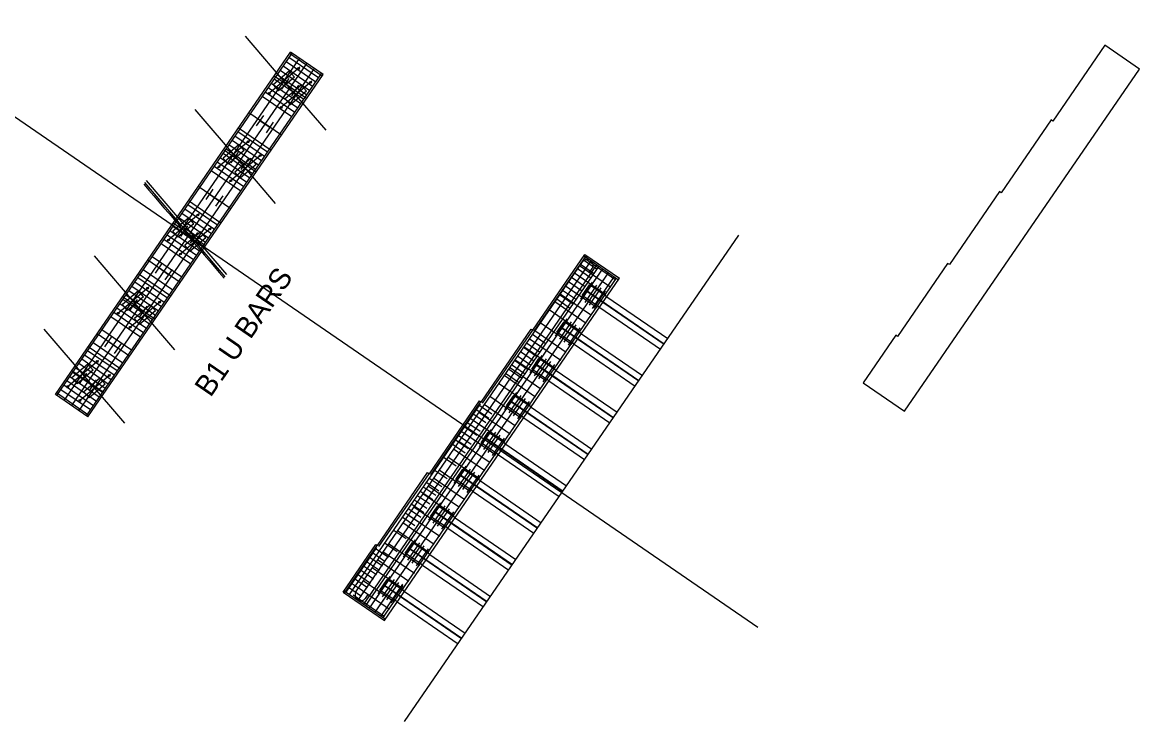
# Model space of a CAD drawing. Extents: x 2378999 to 2381348, y 331302 to 333122.
# Drawn here: x 2379615.5 to 2379721.8, y 332001.2 to 332067.7 of the extents above; entities that cross this region are included whole.
import ezdxf

# ---------------------------------------------------------------- set-up
doc = ezdxf.new("R2010")
doc.units = 0
for name, color, linetype in [('Arrowhead Terminators', 7, 'Continuous'), ('Dimension Lines', 7, 'Continuous'), ('Dimension Lines CELL', 7, 'Continuous'), ('Mis Work Point CELL', 7, 'Continuous'), ('P_SMU_Bent_Cap', 7, 'Continuous'), ('P_SMU_D_Deck_Outline', 7, 'Continuous'), ('P_SMU_Girder_Concrete', 7, 'Continuous'), ('P_SMU_Mis_L_Lines', 7, 'Continuous'), ('P_SMU_Mis_Long_Chord', 7, 'Continuous'), ('P_SMU_Rebar_U_Bar', 7, 'Continuous'), ('Plan Sheet CELL', 7, 'Continuous'), ('Rebar Lines', 7, 'Continuous'), ('Scratch_Level_0', 7, 'Continuous'), ('Sup Concrete Slab Lines', 7, 'Continuous'), ('Text', 7, 'Continuous')]:
    doc.layers.add(name, color=color, linetype=linetype)

msp = doc.modelspace()

# ---------------------------------------------------------------- linework, layer by layer
at = {"layer": 'Arrowhead Terminators'}
for p, q in [((2379647.28, 332013.54), (2379668.84, 332044.91)), ((2379647.48, 332012.73), (2379669.65, 332045.02)), ((2379648.03, 332012.36), (2379670.2, 332044.64)), ((2379648.23, 332012.22), (2379670.41, 332044.5)), ((2379648.57, 332011.98), (2379670.75, 332044.26)), ((2379669.5, 332043.92), (2379669.75, 332044.28)), ((2379649.12, 332011.6), (2379671.3, 332043.88)), ((2379649.88, 332011.08), (2379672.06, 332043.36)), ((2379646.68, 332013.28), (2379659.13, 332031.42)), ((2379646.36, 332013.5), (2379649.28, 332017.76)), ((2379648.19, 332012.91), (2379648.44, 332013.27))]:
    msp.add_line(p, q, dxfattribs=at)
for centre, start, end in [((2379669.29, 332044.6), 325.5093, 145.5093), ((2379647.74, 332013.23), 145.5093, 325.5093)]:
    msp.add_arc(centre, 0.552, start, end, dxfattribs=at)
at = {"layer": 'Dimension Lines'}
for p, q in [((2379669.01, 332045.26), (2379672, 332043.2)), ((2379668.54, 332044.57), (2379671.53, 332042.52)), ((2379668.07, 332043.88), (2379671.05, 332041.83)), ((2379667.22, 332042.65), (2379670.21, 332040.59)), ((2379668.66, 332041.36), (2379669.79, 332043)), ((2379669.07, 332041.07), (2379670.2, 332042.72)), ((2379669.48, 332040.79), (2379670.61, 332042.44)), ((2379669.89, 332040.51), (2379671.02, 332042.15)), ((2379666.18, 332041.14), (2379669.17, 332039.08)), ((2379666.7, 332041.89), (2379669.69, 332039.84)), ((2379665.66, 332040.38), (2379668.65, 332038.33)), ((2379664.81, 332039.14), (2379667.8, 332037.09)), ((2379666.25, 332037.85), (2379667.38, 332039.5)), ((2379666.66, 332037.57), (2379667.79, 332039.22)), ((2379667.07, 332037.29), (2379668.21, 332038.93)), ((2379664.29, 332038.39), (2379667.28, 332036.34)), ((2379667.49, 332037), (2379668.62, 332038.65)), ((2379663.25, 332036.88), (2379666.24, 332034.82)), ((2379663.77, 332037.63), (2379666.76, 332035.58)), ((2379662.4, 332035.64), (2379665.39, 332033.59)), ((2379663.84, 332034.35), (2379664.98, 332036)), ((2379664.25, 332034.07), (2379665.39, 332035.71)), ((2379661.89, 332034.89), (2379664.87, 332032.83)), ((2379664.67, 332033.78), (2379665.8, 332035.43)), ((2379665.08, 332033.5), (2379666.21, 332035.15)), ((2379661.37, 332034.13), (2379664.35, 332032.08)), ((2379660.85, 332033.37), (2379663.84, 332031.32)), ((2379661.44, 332030.85), (2379662.57, 332032.49)), ((2379659.48, 332031.38), (2379662.47, 332029.33)), ((2379660, 332032.14), (2379662.99, 332030.09)), ((2379661.85, 332030.56), (2379662.98, 332032.21)), ((2379662.26, 332030.28), (2379663.39, 332031.93)), ((2379662.67, 332030), (2379663.8, 332031.65)), ((2379658.96, 332030.63), (2379661.95, 332028.57)), ((2379658.44, 332029.87), (2379661.43, 332027.82)), ((2379657.59, 332028.63), (2379660.58, 332026.58)), ((2379659.03, 332027.34), (2379660.16, 332028.99)), ((2379659.44, 332027.06), (2379660.57, 332028.71)), ((2379659.85, 332026.78), (2379660.99, 332028.43)), ((2379657.07, 332027.88), (2379660.06, 332025.83)), ((2379660.27, 332026.49), (2379661.4, 332028.14)), ((2379656.03, 332026.37), (2379659.02, 332024.32)), ((2379656.55, 332027.12), (2379659.54, 332025.07)), ((2379655.18, 332025.13), (2379658.17, 332023.08)), ((2379656.62, 332023.84), (2379657.76, 332025.49)), ((2379657.03, 332023.56), (2379658.17, 332025.21)), ((2379654.67, 332024.38), (2379657.65, 332022.32)), ((2379657.45, 332023.27), (2379658.58, 332024.92)), ((2379657.86, 332022.99), (2379658.99, 332024.64)), ((2379654.15, 332023.62), (2379657.13, 332021.57)), ((2379653.63, 332022.87), (2379656.62, 332020.81)), ((2379654.22, 332020.34), (2379655.35, 332021.99)), ((2379652.26, 332020.87), (2379655.25, 332018.82)), ((2379652.78, 332021.63), (2379655.77, 332019.58)), ((2379654.63, 332020.05), (2379655.76, 332021.7)), ((2379655.04, 332019.77), (2379656.17, 332021.42)), ((2379655.45, 332019.49), (2379656.58, 332021.14)), ((2379651.74, 332020.12), (2379654.73, 332018.07)), ((2379651.22, 332019.36), (2379654.21, 332017.31)), ((2379650.37, 332018.13), (2379653.36, 332016.07)), ((2379651.81, 332016.83), (2379652.94, 332018.48)), ((2379652.22, 332016.55), (2379653.35, 332018.2)), ((2379652.63, 332016.27), (2379653.77, 332017.92)), ((2379653.05, 332015.99), (2379654.18, 332017.63)), ((2379649.33, 332016.62), (2379652.32, 332014.56)), ((2379649.85, 332017.37), (2379652.84, 332015.32)), ((2379648.81, 332015.86), (2379651.8, 332013.81)), ((2379647.96, 332014.62), (2379650.95, 332012.57)), ((2379649.4, 332013.33), (2379650.54, 332014.98)), ((2379649.81, 332013.05), (2379650.95, 332014.7)), ((2379650.23, 332012.77), (2379651.36, 332014.41)), ((2379647.49, 332013.94), (2379650.48, 332011.88)), ((2379650.64, 332012.48), (2379651.77, 332014.13)), ((2379647.02, 332013.25), (2379650.01, 332011.2))]:
    msp.add_line(p, q, dxfattribs=at)
at = {"layer": 'Dimension Lines CELL'}
msp.add_line((2379507.79, 332132.25), (2379685.49, 332010.16), dxfattribs=at)
at = {"layer": 'Mis Work Point CELL'}
for p, q in [((2379619.54, 332031.73), (2379641.91, 332064.28)), ((2379620.24, 332031.25), (2379642.6, 332063.8)), ((2379643.3, 332063.32), (2379620.93, 332030.77)), ((2379651.9, 332001.18), (2379683.69, 332047.45))]:
    msp.add_line(p, q, dxfattribs=at)
at = {"layer": 'P_SMU_Bent_Cap'}
for p, q in [((2379641.95, 332063.43), (2379638.91, 332060.83)), ((2379643.09, 332062.1), (2379640.04, 332059.5)), ((2379637.16, 332056.46), (2379634.12, 332053.86)), ((2379638.3, 332055.13), (2379635.26, 332052.53)), ((2379632.37, 332049.49), (2379629.33, 332046.89)), ((2379633.51, 332048.16), (2379630.47, 332045.56)), ((2379627.59, 332042.52), (2379624.54, 332039.92)), ((2379628.72, 332041.19), (2379625.68, 332038.59)), ((2379622.8, 332035.55), (2379619.76, 332032.95)), ((2379623.93, 332034.22), (2379620.89, 332031.62))]:
    msp.add_line(p, q, dxfattribs=at)
at = {"layer": 'P_SMU_D_Deck_Outline'}
for p, q in [((2379640.94, 332063.06), (2379639.42, 332061.76)), ((2379641.43, 332062.49), (2379639.91, 332061.19)), ((2379641.43, 332062.49), (2379640.94, 332063.06)), ((2379639.91, 332061.19), (2379639.42, 332061.76)), ((2379642.08, 332061.73), (2379640.56, 332060.43)), ((2379642.57, 332061.16), (2379641.05, 332059.86)), ((2379642.57, 332061.16), (2379642.08, 332061.73)), ((2379641.05, 332059.86), (2379640.56, 332060.43)), ((2379636.16, 332056.09), (2379634.64, 332054.79)), ((2379636.64, 332055.52), (2379636.16, 332056.09)), ((2379635.12, 332054.22), (2379634.64, 332054.79)), ((2379636.64, 332055.52), (2379635.12, 332054.22)), ((2379637.29, 332054.76), (2379635.77, 332053.46)), ((2379637.78, 332054.19), (2379637.29, 332054.76)), ((2379637.78, 332054.19), (2379636.26, 332052.89)), ((2379636.26, 332052.89), (2379635.77, 332053.46)), ((2379631.37, 332049.12), (2379629.85, 332047.83)), ((2379631.86, 332048.55), (2379630.34, 332047.26)), ((2379631.86, 332048.55), (2379631.37, 332049.12)), ((2379630.34, 332047.26), (2379629.85, 332047.83)), ((2379632.51, 332047.79), (2379630.99, 332046.5)), ((2379632.99, 332047.22), (2379632.51, 332047.79)), ((2379631.47, 332045.92), (2379630.99, 332046.5)), ((2379632.99, 332047.22), (2379631.47, 332045.92)), ((2379626.58, 332042.16), (2379625.06, 332040.86)), ((2379627.07, 332041.59), (2379626.58, 332042.16)), ((2379627.07, 332041.59), (2379625.55, 332040.29)), ((2379625.55, 332040.29), (2379625.06, 332040.86)), ((2379627.72, 332040.83), (2379626.2, 332039.53)), ((2379628.21, 332040.26), (2379626.69, 332038.96)), ((2379628.21, 332040.26), (2379627.72, 332040.83)), ((2379626.69, 332038.96), (2379626.2, 332039.53)), ((2379621.79, 332035.19), (2379620.27, 332033.89)), ((2379622.28, 332034.62), (2379620.76, 332033.32)), ((2379622.28, 332034.62), (2379621.79, 332035.19)), ((2379620.76, 332033.32), (2379620.27, 332033.89)), ((2379622.93, 332033.86), (2379621.41, 332032.56)), ((2379623.42, 332033.29), (2379622.93, 332033.86)), ((2379621.9, 332031.99), (2379621.41, 332032.56)), ((2379623.42, 332033.29), (2379621.9, 332031.99))]:
    msp.add_line(p, q, dxfattribs=at)
for centre in [(2379641.82, 332063.32), (2379642.96, 332061.99), (2379639.03, 332060.94), (2379640.17, 332059.61), (2379637.03, 332056.35), (2379638.17, 332055.02), (2379634.25, 332053.97), (2379635.38, 332052.64), (2379632.25, 332049.38), (2379633.38, 332048.05), (2379629.46, 332047), (2379630.6, 332045.67), (2379627.46, 332042.41), (2379628.6, 332041.08), (2379624.67, 332040.03), (2379625.81, 332038.7), (2379622.67, 332035.44), (2379623.81, 332034.11), (2379619.88, 332033.06), (2379621.02, 332031.73)]:
    msp.add_circle(centre, 0.0833, dxfattribs=at)
at = {"layer": 'P_SMU_Girder_Concrete'}
for p, q in [((2379640.24, 332061.36), (2379640.93, 332062.36)), ((2379640.58, 332061.86), (2379641.51, 332061.22)), ((2379641.17, 332060.71), (2379641.86, 332061.72)), ((2379637.83, 332057.85), (2379638.52, 332058.86)), ((2379638.17, 332058.35), (2379639.11, 332057.71)), ((2379638.76, 332057.21), (2379639.45, 332058.21)), ((2379635.42, 332054.35), (2379636.11, 332055.35)), ((2379635.77, 332054.85), (2379636.7, 332054.21)), ((2379636.36, 332053.71), (2379637.05, 332054.71)), ((2379633.02, 332050.85), (2379633.71, 332051.85)), ((2379633.36, 332051.35), (2379634.29, 332050.71)), ((2379633.95, 332050.21), (2379634.64, 332051.21)), ((2379630.61, 332047.34), (2379631.3, 332048.35)), ((2379630.95, 332047.85), (2379631.89, 332047.2)), ((2379631.54, 332046.7), (2379632.23, 332047.71)), ((2379628.2, 332043.84), (2379628.89, 332044.84)), ((2379628.55, 332044.34), (2379629.48, 332043.7)), ((2379629.14, 332043.2), (2379629.83, 332044.2)), ((2379668.81, 332041.73), (2379669.5, 332042.73)), ((2379669.14, 332042.21), (2379676.58, 332037.1)), ((2379669.17, 332042.24), (2379676.6, 332037.13)), ((2379671.15, 332041.6), (2379669.5, 332042.73)), ((2379625.8, 332040.34), (2379626.49, 332041.34)), ((2379670.46, 332040.59), (2379668.81, 332041.73)), ((2379671.15, 332041.6), (2379676.93, 332037.62)), ((2379626.14, 332040.84), (2379627.07, 332040.2)), ((2379626.73, 332039.7), (2379627.42, 332040.7)), ((2379670.46, 332040.59), (2379676.25, 332036.62)), ((2379666.4, 332038.22), (2379667.09, 332039.23)), ((2379668.74, 332038.09), (2379667.09, 332039.23)), ((2379623.39, 332036.84), (2379624.08, 332037.84)), ((2379668.05, 332037.09), (2379666.4, 332038.22)), ((2379666.73, 332038.71), (2379674.17, 332033.6)), ((2379666.76, 332038.74), (2379674.2, 332033.63)), ((2379668.74, 332038.09), (2379674.53, 332034.12)), ((2379623.73, 332037.34), (2379624.67, 332036.7)), ((2379624.32, 332036.19), (2379625.01, 332037.2)), ((2379668.05, 332037.09), (2379673.84, 332033.11)), ((2379664, 332034.72), (2379664.68, 332035.72)), ((2379666.33, 332034.59), (2379664.68, 332035.72)), ((2379665.64, 332033.59), (2379664, 332034.72)), ((2379664.33, 332035.2), (2379671.77, 332030.09)), ((2379664.35, 332035.24), (2379671.79, 332030.13)), ((2379666.33, 332034.59), (2379672.12, 332030.61)), ((2379620.98, 332033.33), (2379621.67, 332034.34)), ((2379621.33, 332033.83), (2379622.26, 332033.19)), ((2379621.92, 332032.69), (2379622.61, 332033.69)), ((2379665.64, 332033.59), (2379671.43, 332029.61)), ((2379661.59, 332031.22), (2379662.28, 332032.22)), ((2379661.92, 332031.7), (2379669.36, 332026.59)), ((2379661.95, 332031.74), (2379669.38, 332026.63)), ((2379663.93, 332031.09), (2379662.28, 332032.22)), ((2379663.24, 332030.08), (2379661.59, 332031.22)), ((2379663.93, 332031.09), (2379669.71, 332027.11)), ((2379663.24, 332030.08), (2379669.03, 332026.11)), ((2379659.18, 332027.71), (2379659.87, 332028.72)), ((2379659.52, 332028.2), (2379666.95, 332023.09)), ((2379659.54, 332028.23), (2379666.98, 332023.12)), ((2379661.52, 332027.58), (2379659.87, 332028.72)), ((2379660.83, 332026.58), (2379659.18, 332027.71)), ((2379661.52, 332027.58), (2379667.31, 332023.61)), ((2379660.83, 332026.58), (2379666.62, 332022.6)), ((2379656.78, 332024.21), (2379657.46, 332025.21)), ((2379659.11, 332024.08), (2379657.46, 332025.21)), ((2379658.42, 332023.08), (2379656.78, 332024.21)), ((2379657.11, 332024.69), (2379664.55, 332019.59)), ((2379657.13, 332024.73), (2379664.57, 332019.62)), ((2379659.11, 332024.08), (2379664.9, 332020.1)), ((2379658.42, 332023.08), (2379664.21, 332019.1)), ((2379654.37, 332020.71), (2379655.06, 332021.71)), ((2379654.7, 332021.19), (2379662.14, 332016.08)), ((2379654.73, 332021.23), (2379662.16, 332016.12)), ((2379656.71, 332020.58), (2379655.06, 332021.71)), ((2379656.02, 332019.58), (2379654.37, 332020.71)), ((2379656.71, 332020.58), (2379662.5, 332016.6)), ((2379656.02, 332019.58), (2379661.81, 332015.6)), ((2379651.96, 332017.2), (2379652.65, 332018.21)), ((2379652.3, 332017.69), (2379659.73, 332012.58)), ((2379652.32, 332017.72), (2379659.76, 332012.61)), ((2379654.3, 332017.07), (2379652.65, 332018.21)), ((2379653.61, 332016.07), (2379651.96, 332017.2)), ((2379654.3, 332017.07), (2379660.09, 332013.1)), ((2379653.61, 332016.07), (2379659.4, 332012.1)), ((2379649.56, 332013.7), (2379650.24, 332014.7)), ((2379651.89, 332013.57), (2379650.24, 332014.7)), ((2379651.2, 332012.57), (2379649.56, 332013.7)), ((2379649.89, 332014.19), (2379657.33, 332009.08)), ((2379649.91, 332014.22), (2379657.35, 332009.11)), ((2379651.89, 332013.57), (2379657.68, 332009.6)), ((2379651.2, 332012.57), (2379656.99, 332008.59))]:
    msp.add_line(p, q, dxfattribs=at)
at = {"layer": 'P_SMU_Mis_L_Lines'}
for p, q in [((2379641, 332061.46), (2379636.78, 332066.4)), ((2379644.43, 332057.45), (2379641, 332061.46)), ((2379636.21, 332054.49), (2379631.99, 332059.43)), ((2379639.64, 332050.48), (2379636.21, 332054.49)), ((2379631.42, 332047.52), (2379627.2, 332052.46)), ((2379634.85, 332043.51), (2379631.42, 332047.52)), ((2379626.63, 332040.56), (2379622.42, 332045.49)), ((2379630.06, 332036.54), (2379626.63, 332040.56)), ((2379621.85, 332033.59), (2379617.63, 332038.52)), ((2379625.28, 332029.57), (2379621.85, 332033.59))]:
    msp.add_line(p, q, dxfattribs=at)
at = {"layer": 'P_SMU_Mis_Long_Chord'}
msp.add_arc((2385014.25, 336646.34), 7080, 220.456783, 220.552053, dxfattribs=at)
at = {"layer": 'P_SMU_Rebar_U_Bar'}
for p, q in [((2379643.73, 332062.42), (2379640.91, 332064.36)), ((2379643.16, 332061.6), (2379640.35, 332063.53)), ((2379643.45, 332062.01), (2379640.63, 332063.95)), ((2379642.31, 332060.36), (2379639.5, 332062.3)), ((2379642.6, 332060.78), (2379639.78, 332062.71)), ((2379642.88, 332061.19), (2379640.06, 332063.12)), ((2379641.75, 332059.54), (2379638.93, 332061.47)), ((2379642.03, 332059.95), (2379639.21, 332061.89)), ((2379641.18, 332058.71), (2379638.37, 332060.65)), ((2379641.46, 332059.13), (2379638.65, 332061.06)), ((2379638.87, 332055.35), (2379636.05, 332057.28)), ((2379638.02, 332054.11), (2379635.2, 332056.05)), ((2379638.3, 332054.52), (2379635.49, 332056.46)), ((2379638.59, 332054.94), (2379635.77, 332056.87)), ((2379637.17, 332052.88), (2379634.35, 332054.81)), ((2379637.45, 332053.29), (2379634.64, 332055.22)), ((2379637.74, 332053.7), (2379634.92, 332055.64)), ((2379636.6, 332052.05), (2379633.79, 332053.99)), ((2379636.89, 332052.46), (2379634.07, 332054.4)), ((2379636.32, 332051.64), (2379633.51, 332053.57)), ((2379633.54, 332047.59), (2379630.72, 332049.52)), ((2379633.82, 332048), (2379631, 332049.93)), ((2379634.1, 332048.41), (2379631.29, 332050.35)), ((2379632.97, 332046.76), (2379630.15, 332048.7)), ((2379633.25, 332047.18), (2379630.44, 332049.11)), ((2379632.12, 332045.53), (2379629.31, 332047.46)), ((2379632.4, 332045.94), (2379629.59, 332047.87)), ((2379632.69, 332046.35), (2379629.87, 332048.29)), ((2379631.56, 332044.7), (2379628.74, 332046.64)), ((2379631.84, 332045.11), (2379629.02, 332047.05)), ((2379630.71, 332043.47), (2379627.89, 332045.4)), ((2379629.86, 332042.23), (2379627.04, 332044.16)), ((2379668.35, 332044.3), (2379669.59, 332043.45)), ((2379668.63, 332044.71), (2379669.87, 332043.86)), ((2379668.81, 332043.78), (2379669.65, 332045.02)), ((2379668.92, 332045.12), (2379670.15, 332044.27)), ((2379669.35, 332043.4), (2379670.2, 332044.64)), ((2379669.9, 332043.03), (2379670.75, 332044.26)), ((2379629.34, 332041.47), (2379626.52, 332043.41)), ((2379667.78, 332043.47), (2379669.02, 332042.62)), ((2379668.07, 332043.88), (2379669.3, 332043.03)), ((2379669.78, 332040.48), (2379671.85, 332043.51)), ((2379670.45, 332042.65), (2379671.3, 332043.88)), ((2379628.49, 332040.24), (2379625.67, 332042.17)), ((2379628.77, 332040.65), (2379625.95, 332042.59)), ((2379629.05, 332041.06), (2379626.24, 332043)), ((2379666.93, 332042.23), (2379668.17, 332041.39)), ((2379667.22, 332042.65), (2379668.45, 332041.8)), ((2379667.5, 332043.06), (2379668.74, 332042.21)), ((2379627.92, 332039.41), (2379625.11, 332041.35)), ((2379628.2, 332039.83), (2379625.39, 332041.76)), ((2379666.37, 332041.41), (2379667.6, 332040.56)), ((2379666.65, 332041.82), (2379667.89, 332040.97)), ((2379627.07, 332038.18), (2379624.26, 332040.11)), ((2379627.36, 332038.59), (2379624.54, 332040.52)), ((2379627.64, 332039), (2379624.82, 332040.94)), ((2379626.79, 332037.77), (2379623.97, 332039.7)), ((2379625.94, 332036.53), (2379623.12, 332038.46)), ((2379664.06, 332038.04), (2379665.29, 332037.2)), ((2379625.09, 332035.29), (2379622.27, 332037.23)), ((2379663.21, 332036.81), (2379664.44, 332035.96)), ((2379663.49, 332037.22), (2379664.73, 332036.37)), ((2379663.77, 332037.63), (2379665.01, 332036.78)), ((2379624, 332033.71), (2379621.19, 332035.65)), ((2379624.29, 332034.13), (2379621.47, 332036.06)), ((2379624.57, 332034.54), (2379621.75, 332036.47)), ((2379662.64, 332035.98), (2379663.88, 332035.13)), ((2379662.92, 332036.4), (2379664.16, 332035.55)), ((2379623.44, 332032.89), (2379620.62, 332034.82)), ((2379623.72, 332033.3), (2379620.91, 332035.24)), ((2379661.79, 332034.75), (2379663.03, 332033.9)), ((2379662.07, 332035.16), (2379663.31, 332034.31)), ((2379662.36, 332035.57), (2379663.59, 332034.72)), ((2379622.59, 332031.65), (2379619.77, 332033.59)), ((2379622.87, 332032.06), (2379620.06, 332034)), ((2379623.16, 332032.48), (2379620.34, 332034.41)), ((2379661.51, 332034.34), (2379662.74, 332033.49)), ((2379622.02, 332030.83), (2379619.21, 332032.76)), ((2379622.31, 332031.24), (2379619.49, 332033.18)), ((2379658.41, 332030.5), (2379659.64, 332029.65)), ((2379658.69, 332030.91), (2379659.93, 332030.06)), ((2379658.97, 332031.33), (2379660.21, 332030.48)), ((2379657.56, 332029.27), (2379658.79, 332028.42)), ((2379657.84, 332029.68), (2379659.08, 332028.83)), ((2379658.12, 332030.09), (2379659.36, 332029.24)), ((2379656.99, 332028.44), (2379658.23, 332027.59)), ((2379657.27, 332028.85), (2379658.51, 332028)), ((2379656.42, 332027.62), (2379657.66, 332026.77)), ((2379656.71, 332028.03), (2379657.94, 332027.18)), ((2379655.57, 332026.38), (2379656.81, 332025.53)), ((2379654.72, 332025.14), (2379655.96, 332024.3)), ((2379653.92, 332023.98), (2379655.16, 332023.13)), ((2379654.21, 332024.39), (2379655.44, 332023.54)), ((2379653.36, 332023.15), (2379654.59, 332022.3)), ((2379653.64, 332023.56), (2379654.88, 332022.72)), ((2379652.51, 332021.92), (2379653.74, 332021.07)), ((2379652.79, 332022.33), (2379654.03, 332021.48)), ((2379653.07, 332022.74), (2379654.31, 332021.89)), ((2379651.94, 332021.09), (2379653.18, 332020.24)), ((2379652.22, 332021.5), (2379653.46, 332020.65)), ((2379651.66, 332020.68), (2379652.89, 332019.83)), ((2379650.81, 332019.44), (2379652.04, 332018.59)), ((2379649.12, 332017.67), (2379650.36, 332016.82)), ((2379649.96, 332018.21), (2379651.19, 332017.36)), ((2379648.55, 332016.85), (2379649.79, 332016)), ((2379648.84, 332017.26), (2379650.07, 332016.41)), ((2379647.7, 332015.61), (2379648.94, 332014.76)), ((2379647.99, 332016.02), (2379649.22, 332015.17)), ((2379648.27, 332016.43), (2379649.51, 332015.59)), ((2379646.68, 332013.28), (2379647.53, 332014.52)), ((2379647.14, 332014.79), (2379648.37, 332013.94)), ((2379647.42, 332015.2), (2379648.66, 332014.35)), ((2379646.57, 332013.96), (2379647.81, 332013.11)), ((2379646.86, 332014.37), (2379648.09, 332013.52)), ((2379647.48, 332012.73), (2379648.33, 332013.97)), ((2379648.03, 332012.36), (2379648.87, 332013.59)), ((2379649.67, 332011.22), (2379651.75, 332014.25)), ((2379648.57, 332011.98), (2379649.42, 332013.22)), ((2379649.12, 332011.6), (2379649.97, 332012.84))]:
    msp.add_line(p, q, dxfattribs=at)
at = {"layer": 'Plan Sheet CELL'}
msp.add_line((2379635, 332043.72), (2379627.35, 332052.67), dxfattribs=at)
at = {"layer": 'Rebar Lines'}
for p, q in [((2379642.59, 332060.47), (2379639.5, 332062.6)), ((2379640.19, 332056.97), (2379637.1, 332059.1)), ((2379637.78, 332053.47), (2379634.69, 332055.59)), ((2379635.37, 332049.97), (2379632.28, 332052.09)), ((2379632.97, 332046.46), (2379629.88, 332048.59)), ((2379630.56, 332042.96), (2379627.47, 332045.08)), ((2379669.15, 332042.23), (2379676.59, 332037.12)), ((2379628.15, 332039.46), (2379625.06, 332041.58)), ((2379625.75, 332035.95), (2379622.66, 332038.08)), ((2379666.75, 332038.72), (2379674.18, 332033.61)), ((2379623.34, 332032.45), (2379620.25, 332034.57)), ((2379664.34, 332035.22), (2379671.78, 332030.11)), ((2379661.93, 332031.72), (2379669.37, 332026.61)), ((2379659.53, 332028.21), (2379666.96, 332023.11)), ((2379657.12, 332024.71), (2379664.56, 332019.6)), ((2379654.71, 332021.21), (2379662.15, 332016.1)), ((2379652.31, 332017.71), (2379659.74, 332012.6)), ((2379649.9, 332014.2), (2379657.34, 332009.09))]:
    msp.add_line(p, q, dxfattribs=at)
at = {"layer": 'Scratch_Level_0'}
for p, q in [((2379618.83, 332032.21), (2379641.2, 332064.77)), ((2379644.06, 332062.6), (2379640.97, 332064.73)), ((2379621.65, 332030.28), (2379644.01, 332062.84)), ((2379664.24, 332038.32), (2379669.2, 332045.53)), ((2379668.97, 332045.49), (2379672.26, 332043.22)), ((2379659.32, 332031.49), (2379664.09, 332038.43)), ((2379621.88, 332030.32), (2379618.79, 332032.45)), ((2379654.39, 332024.66), (2379659.16, 332031.6)), ((2379649.47, 332017.84), (2379654.23, 332024.77)), ((2379646.19, 332013.41), (2379649.31, 332017.95)), ((2379646.15, 332013.64), (2379650.09, 332010.94))]:
    msp.add_line(p, q, dxfattribs=at)
at = {"layer": 'Text'}
for p, q in [((2379618.69, 332032.31), (2379641.06, 332064.86)), ((2379644.15, 332062.74), (2379641.06, 332064.86)), ((2379621.78, 332030.18), (2379644.15, 332062.74)), ((2379639.2, 332055.53), (2379636.1, 332057.65)), ((2379634.43, 332048.59), (2379631.34, 332050.72)), ((2379664.11, 332038.41), (2379669.06, 332045.63)), ((2379669.06, 332045.63), (2379672.36, 332043.36)), ((2379629.66, 332041.66), (2379626.57, 332043.78)), ((2379649.99, 332010.8), (2379672.36, 332043.36)), ((2379659.18, 332031.59), (2379663.95, 332038.52)), ((2379663.95, 332038.52), (2379664.11, 332038.41)), ((2379624.9, 332034.72), (2379621.81, 332036.84)), ((2379621.78, 332030.18), (2379618.69, 332032.31)), ((2379654.26, 332024.76), (2379659.02, 332031.7)), ((2379659.02, 332031.7), (2379659.18, 332031.59)), ((2379649.33, 332017.93), (2379654.1, 332024.87)), ((2379654.1, 332024.87), (2379654.26, 332024.76)), ((2379646.06, 332013.51), (2379649.17, 332018.04)), ((2379649.17, 332018.04), (2379649.33, 332017.93)), ((2379646.06, 332013.51), (2379649.99, 332010.8))]:
    msp.add_line(p, q, dxfattribs=at)
msp.add_lwpolyline([(2379698.63, 332037.94), (2379695.52, 332033.41), (2379699.45, 332030.71), (2379721.82, 332063.26), (2379718.52, 332065.53), (2379713.57, 332058.32), (2379713.41, 332058.43), (2379708.64, 332051.49), (2379708.49, 332051.6), (2379703.72, 332044.66), (2379703.56, 332044.77), (2379698.79, 332037.83)], close=True, dxfattribs=at)

# ---------------------------------------------------------------- texts
at = {"layer": 'Sup Concrete Slab Lines'}
msp.add_text('B1 U BARS', height=2, rotation=55.5093, dxfattribs=at).set_placement((2379633.45, 332031.96))

doc.saveas('drawing.dxf')
